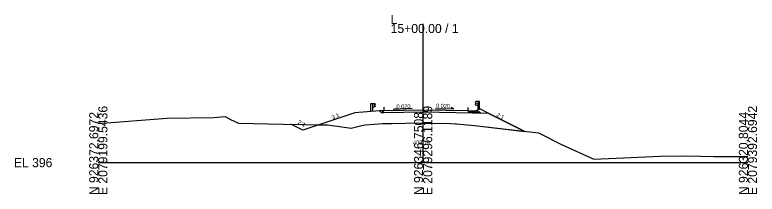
# Model space of a CAD drawing. Extents: x -26 to 10503, y -10 to 9546.
# Drawn here: x 974.3 to 1202.8, y -9.7 to 45.5 of the extents above; entities that cross this region are included whole.
import ezdxf

# ---------------------------------------------------------------- set-up
doc = ezdxf.new("R2010")
doc.units = 0
for name, color, linetype in [('Default', 7, 'Continuous'), ('Exist XS Center Line Elevation Label', 7, 'Continuous'), ('Exist XS Ground Line', 7, 'Continuous'), ('Old_Level_3', 7, 'Continuous'), ('Old_Level_58', 7, 'Continuous'), ('Old_Level_63', 7, 'Continuous'), ('Prop XS Dump Level', 7, 'Continuous'), ('Prop XS EOT Tick Mark', 7, 'Continuous'), ('Prop XS Finish Grade', 7, 'Continuous'), ('Prop XS Finish Grade CurbGutter', 7, 'Continuous'), ('Prop XS Finish Grade Earthwork', 7, 'Continuous'), ('Prop XS Finish Grade Pavement', 7, 'Continuous'), ('Prop XS Pvmt Edge Slope', 7, 'Continuous'), ('Prop XS SE Text', 7, 'Continuous'), ('Prop XS Side Slope Text', 7, 'Continuous'), ('Prop XS Subgrade CurbGutter', 7, 'Continuous'), ('Prop XS Subgrade Earthwork', 7, 'Continuous')]:
    doc.layers.add(name, color=color, linetype=linetype)

msp = doc.modelspace()

# ---------------------------------------------------------------- linework, layer by layer
at = {"layer": 'Default'}
for points in [[(1078.99, 15.35), (1067.9, 11.65), (1070.57, 11.6), (1074.21, 11.17), (1077.81, 10.58), (1081.17, 11.39), (1082.14, 11.64), (1084.88, 11.86), (1087.54, 12.06), (1090.5, 12.1), (1098.69, 12.22), (1100, 12.19), (1101.44, 12.16), (1108.43, 12.01), (1109.83, 11.94), (1110.24, 11.92), (1115.78, 11.39), (1131.32, 9.62), (1120.25, 15.15), (1100, 15.56), (1088, 15.32), (1087.23, 15.3), (1086.58, 15.96)], [(1059.28, 11.83), (1067.9, 11.65), (1062.95, 10)]]:
    msp.add_lwpolyline(points, close=True, dxfattribs=at)
at = {"layer": 'Exist XS Ground Line'}
for p, q in [((1021.23, 13.66), (1035.44, 13.95)), ((1035.44, 13.95), (1039.03, 14.23)), ((1039.03, 14.23), (1040.71, 13.31)), ((1000, 12.07), (1021.23, 13.66)), ((1040.71, 13.31), (1043.21, 12.11)), ((1043.21, 12.11), (1056.95, 11.88)), ((1056.95, 11.88), (1070.57, 11.6)), ((1070.57, 11.6), (1074.21, 11.17)), ((1081.17, 11.39), (1082.14, 11.64)), ((1082.14, 11.64), (1084.88, 11.86)), ((1084.88, 11.86), (1087.54, 12.06)), ((1087.54, 12.06), (1090.5, 12.1)), ((1090.5, 12.1), (1098.69, 12.22)), ((1098.69, 12.22), (1100, 12.19)), ((1100, 12.19), (1101.44, 12.16)), ((1101.44, 12.16), (1108.43, 12.01)), ((1108.43, 12.01), (1109.83, 11.94)), ((1109.83, 11.94), (1110.24, 11.92)), ((1110.24, 11.92), (1115.78, 11.39)), ((1074.21, 11.17), (1077.81, 10.58)), ((1077.81, 10.58), (1081.17, 11.39)), ((1115.78, 11.39), (1135.53, 9.14)), ((1135.53, 9.14), (1142.64, 5.57)), ((1142.64, 5.57), (1152.51, 1.04)), ((1152.51, 1.04), (1173.05, 2.04)), ((1173.05, 2.04), (1181.47, 2.07)), ((1181.47, 2.07), (1189.5, 1.93)), ((1189.5, 1.93), (1200, 1.85))]:
    msp.add_line(p, q, dxfattribs=at)
at = {"layer": 'Old_Level_3'}
for p, q in [((1116.1, 18.58), (1116.07, 18.52)), ((1116.07, 18.52), (1116.1, 18.46)), ((1116.39, 18.78), (1116.1, 18.58)), ((1116.1, 18.46), (1116.39, 18.26)), ((1116.89, 18.78), (1116.39, 18.78)), ((1117.39, 18.78), (1116.89, 18.78)), ((1116.89, 18.78), (1116.89, 16.31)), ((1117.39, 16.56), (1117.39, 18.78)), ((1083.91, 15.76), (1083.91, 18.26)), ((1083.91, 18.26), (1084.41, 18.26)), ((1084.41, 18.26), (1084.41, 15.76)), ((1084.41, 18.26), (1084.91, 18.26)), ((1084.91, 17.13), (1084.41, 17.13)), ((1084.91, 18.26), (1085.2, 18.06)), ((1085.2, 17.94), (1084.91, 17.74)), ((1084.91, 17.74), (1084.91, 17.65)), ((1084.91, 17.65), (1085.2, 17.45)), ((1085.2, 17.33), (1084.91, 17.13)), ((1085.2, 18.06), (1085.23, 18)), ((1085.23, 18), (1085.2, 17.94)), ((1085.2, 17.45), (1085.23, 17.39)), ((1085.23, 17.39), (1085.2, 17.33)), ((1116.1, 17.97), (1116.07, 17.91)), ((1116.07, 17.91), (1116.1, 17.85)), ((1116.39, 18.17), (1116.1, 17.97)), ((1116.1, 17.85), (1116.39, 17.65)), ((1116.39, 18.26), (1116.39, 18.17)), ((1116.39, 17.65), (1116.89, 17.65))]:
    msp.add_line(p, q, dxfattribs=at)
at = {"layer": 'Old_Level_63'}
for p, q in [((1100, 0), (1100, 42.7)), ((1000, 0), (1100, 0)), ((1100, 0), (1200, 0))]:
    msp.add_line(p, q, dxfattribs=at)
at = {"layer": 'Prop XS EOT Tick Mark'}
for p, q in [((1088, 16.07), (1088, 17.07)), ((1113.82, 16.03), (1113.82, 17.03))]:
    msp.add_line(p, q, dxfattribs=at)
at = {"layer": 'Prop XS Finish Grade'}
for p, q in [((1088, 16.07), (1086.58, 15.96)), ((1116.84, 16.28), (1117.42, 16.57)), ((1120.25, 15.15), (1117.42, 16.57))]:
    msp.add_line(p, q, dxfattribs=at)
at = {"layer": 'Prop XS Finish Grade CurbGutter'}
for p, q in [((1113.82, 16.03), (1116.15, 15.94)), ((1116.15, 15.94), (1116.84, 16.28))]:
    msp.add_line(p, q, dxfattribs=at)
at = {"layer": 'Prop XS Finish Grade Earthwork'}
for p, q in [((1078.99, 15.35), (1062.95, 10)), ((1086.58, 15.96), (1078.99, 15.35)), ((1120.25, 15.15), (1131.32, 9.62)), ((1062.95, 10), (1059.28, 11.83))]:
    msp.add_line(p, q, dxfattribs=at)
at = {"layer": 'Prop XS Finish Grade Pavement'}
for p, q in [((1088, 16.07), (1100, 16.31)), ((1100, 16.31), (1113.82, 16.03))]:
    msp.add_line(p, q, dxfattribs=at)
at = {"layer": 'Prop XS Pvmt Edge Slope'}
for p, q in [((1088, 16.07), (1087.23, 15.3)), ((1116.84, 15.61), (1117.34, 15.61)), ((1117.34, 15.61), (1117.75, 15.2))]:
    msp.add_line(p, q, dxfattribs=at)
at = {"layer": 'Prop XS SE Text'}
for points in [[(1096.68, 16.62), (1090.93, 16.35), (1091.78, 16.81)], [(1103.77, 16.65), (1109.47, 16.52), (1108.62, 16.98)]]:
    msp.add_lwpolyline(points, dxfattribs=at)
at = {"layer": 'Prop XS Subgrade CurbGutter'}
for p, q in [((1113.82, 16.03), (1113.82, 15.61)), ((1116.84, 15.61), (1116.84, 16.28)), ((1113.82, 15.61), (1116.84, 15.61))]:
    msp.add_line(p, q, dxfattribs=at)
at = {"layer": 'Prop XS Subgrade Earthwork'}
for p, q in [((1087.23, 15.3), (1086.58, 15.96)), ((1088, 15.32), (1087.23, 15.3)), ((1100, 15.56), (1088, 15.32)), ((1120.25, 15.15), (1100, 15.56))]:
    msp.add_line(p, q, dxfattribs=at)

# ---------------------------------------------------------------- texts
at = {"layer": 'Exist XS Center Line Elevation Label'}
msp.add_text('408.19', height=1.25, rotation=360, dxfattribs=at).set_placement((1096.86, 5.57))
at = {"layer": 'Old_Level_58'}
for p in [(1116.89, 16.28), (1084.27, 15.76)]:
    msp.add_text('Case1', height=0.04, dxfattribs=at).set_placement(p)
at = {"layer": 'Old_Level_63'}
for s, p in [('L', (1090, 42.7)), ('15+00.00 / 1', (1090, 39.9)), ('EL 396', (974, -1.4))]:
    msp.add_text(s, height=2.8, dxfattribs=at).set_placement(p)
for s, p in [('E 2079199.5436', (1002.8, -10)), ('E 2079296.1189', (1102.8, -10)), ('E 2079392.6942', (1202.8, -10)), ('N 926372.6972', (1000, -10)), ('N 926346.7508', (1100, -10)), ('N 926320.8044', (1200, -10))]:
    msp.add_text(s, height=2.8, rotation=90, dxfattribs=at).set_placement(p)
at = {"layer": 'Prop XS Dump Level'}
msp.add_text('Case1', height=0.04, dxfattribs=at).set_placement((1080, 15.39))
at = {"layer": 'Prop XS SE Text'}
for rotation, p in [(1.1458, (1091.81, 16.65)), (358.8542, (1103.96, 16.9))]:
    msp.add_text('0.020', height=1.25, rotation=rotation, dxfattribs=at).set_placement(p)
at = {"layer": 'Prop XS Side Slope Text'}
for s, rotation, p in [('3:1', 26.5651, (1072.19, 13.21)), ('2:1', 333.4349, (1122.44, 14.37)), ('2:1', 333.4349, (1061.27, 12.05))]:
    msp.add_text(s, height=1.25, rotation=rotation, dxfattribs=at).set_placement(p)

doc.saveas('drawing.dxf')
